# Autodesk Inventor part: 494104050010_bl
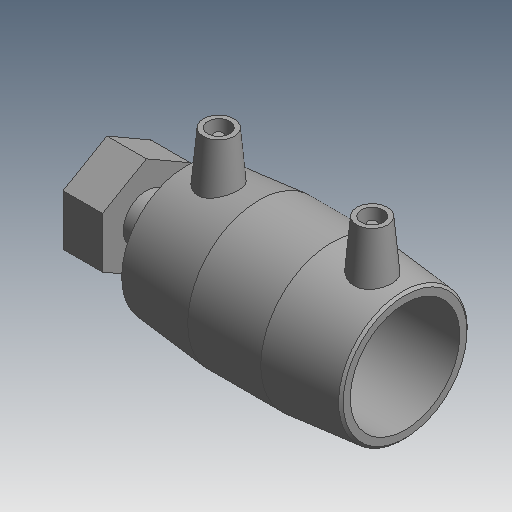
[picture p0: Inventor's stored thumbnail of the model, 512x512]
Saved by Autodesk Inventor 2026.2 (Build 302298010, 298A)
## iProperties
Created: 2017-06
Part Number: 494104050010_bl
Material: Generic
Description: PLASSON FEMALE FREE NUT TRANSITION COUPLER 50X1"
Document SubType Name: Modeling
Designer: KIM
Mass: 55.0731 g
Surface Area: 148.067 cm^2
Volume: 55.0731 cm^3
Density: 1 g/cm^3
Appearance: Default
Author: KIM
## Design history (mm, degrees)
derived "494104.ipt"
feature "Solid1::494104.ipt" dims "ScaleForDerivedMember" = 10
tag "TaggingFeature1"
body "Solid1"
other parameters: "d2" = 65 [user parameter], "d3" = 49 [user parameter], "d4" = 33.33333 [user parameter], "d5" = 58.5 [user parameter], "d6" = 47.5 [user parameter], "d29" = 52 [user parameter], "d30" = 14 [user parameter], "d31" = 35 [user parameter], "d34" = 5 deg [user parameter], "d41" = 4 [user parameter], "d42" = 14 [user parameter], "d43" = 0 [user parameter], "d48" = 3 [user parameter], "d49" = 0 [user parameter], "d55" = 36 [user parameter], "d80" = 1 [user parameter], "d83" = 18 [user parameter], "d84" = 11.88 [user parameter], "d85" = 1.188 [user parameter], "d86" = 24.2328 [user parameter], "d87" = 30.291 [user parameter], "d88" = 33.291 [user parameter], "d89" = 65 [user parameter], "d96" = 21.2037 [user parameter], "d97" = 0 [user parameter], "d98" = 3.0291 [user parameter], "d99" = 3.0291 [user parameter], "d106" = 0 [user parameter], "d107" = 6.5 [user parameter], "L_" = 136 [user parameter], "L_1" = 49 [user parameter], "D_1" = 65 [user parameter], "A_" = 52 [user parameter], "d_2" = 12 [user parameter], "L_2" = 36 [user parameter], "D_" = 19 [user parameter], "G_" = 30.291 [user parameter], "d102" = 33.291 [user parameter]
